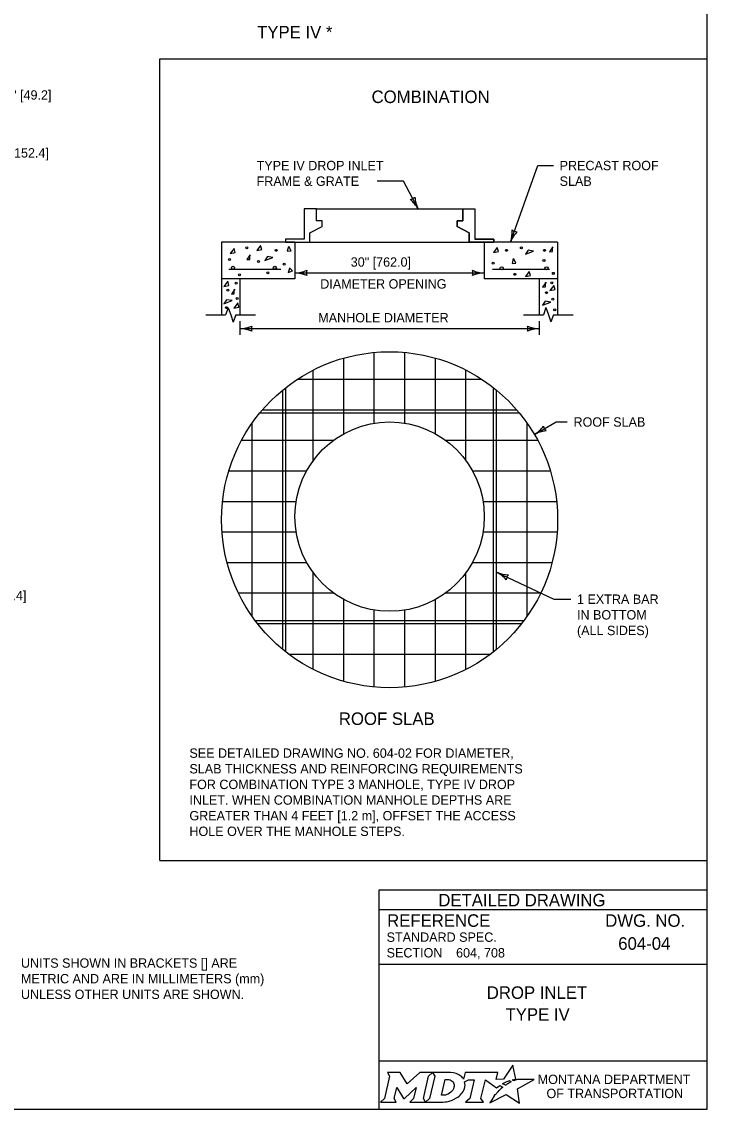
# Model space of a CAD drawing. Extents: x 49991.4 to 50021, y 49987.6 to 50011.4.
# Drawn here: x 50004.23 to 50008.61, y 50000.06 to 50007.02 of the extents above; entities that cross this region are included whole.
import ezdxf

# ---------------------------------------------------------------- set-up
doc = ezdxf.new("R2010")
doc.units = 0
for name, color, linetype in [('Level 1', 7, 'Continuous'), ('Level 2', 7, 'Continuous'), ('Level 3', 7, 'Continuous'), ('Level 6', 7, 'Continuous')]:
    doc.layers.add(name, color=color, linetype=linetype)

msp = doc.modelspace()

# ---------------------------------------------------------------- linework, layer by layer
at = {"layer": 'Level 1'}
for p, q in [((50005.1146, 50006.7794), (50008.6146, 50006.7794)), ((50005.1146, 50001.6533), (50005.1146, 50006.7794)), ((50006.1157, 50005.8205), (50006.0387, 50005.8205)), ((50006.0387, 50005.8205), (50006.0387, 50005.6252)), ((50006.1157, 50005.8205), (50006.0387, 50005.8205)), ((50006.0387, 50005.8205), (50006.0387, 50005.6252)), ((50006.1157, 50005.7436), (50006.1157, 50005.8205)), ((50006.1157, 50005.7436), (50006.1157, 50005.8205)), ((50006.1157, 50005.8205), (50007.0519, 50005.8205)), ((50007.0519, 50005.7436), (50007.0519, 50005.8205)), ((50007.0519, 50005.8205), (50007.1289, 50005.8205)), ((50007.0519, 50005.8205), (50007.0519, 50005.7436)), ((50007.0519, 50005.8205), (50007.1289, 50005.8205)), ((50007.1289, 50005.8205), (50007.1289, 50005.6252)), ((50007.1289, 50005.8205), (50007.1289, 50005.6252)), ((50007.1289, 50005.8205), (50007.1289, 50005.6252)), ((50006.1523, 50005.7436), (50006.1157, 50005.7436)), ((50006.1523, 50005.7436), (50006.1157, 50005.7436)), ((50006.1523, 50005.7062), (50006.1523, 50005.7436)), ((50006.1523, 50005.7062), (50006.1523, 50005.7436)), ((50007.0153, 50005.7062), (50007.0153, 50005.7436)), ((50007.0153, 50005.7436), (50007.0519, 50005.7436)), ((50007.0519, 50005.7436), (50007.0153, 50005.7436)), ((50007.0153, 50005.7436), (50007.0153, 50005.7062)), ((50006.0743, 50005.6671), (50006.1523, 50005.7062)), ((50006.0743, 50005.6671), (50006.1523, 50005.7062)), ((50007.0933, 50005.6671), (50007.0153, 50005.7062)), ((50007.0153, 50005.7062), (50007.0933, 50005.6671)), ((50005.9783, 50005.6078), (50005.5095, 50005.6078)), ((50005.5095, 50005.6078), (50005.5095, 50005.382)), ((50006.0387, 50005.6252), (50005.9179, 50005.6252)), ((50005.9179, 50005.6252), (50005.9179, 50005.6078)), ((50006.0387, 50005.6252), (50005.9179, 50005.6252)), ((50005.9179, 50005.6252), (50005.9179, 50005.6078)), ((50005.9179, 50005.6078), (50006.0743, 50005.6078)), ((50005.9179, 50005.6078), (50006.0743, 50005.6078)), ((50005.9783, 50005.6078), (50005.9783, 50005.3734)), ((50006.0743, 50005.6078), (50006.0743, 50005.6671)), ((50006.0743, 50005.6078), (50006.0743, 50005.6671)), ((50006.0743, 50005.6078), (50007.0933, 50005.6078)), ((50007.0933, 50005.6078), (50007.0933, 50005.6671)), ((50007.0933, 50005.6671), (50007.0933, 50005.6078)), ((50007.2497, 50005.6078), (50007.0933, 50005.6078)), ((50007.0933, 50005.6078), (50007.2497, 50005.6078)), ((50007.1289, 50005.6252), (50007.2497, 50005.6252)), ((50007.2497, 50005.6252), (50007.1289, 50005.6252)), ((50007.6581, 50005.6078), (50007.1893, 50005.6078)), ((50007.1893, 50005.6078), (50007.1893, 50005.3734)), ((50007.2497, 50005.6252), (50007.2497, 50005.6078)), ((50007.2497, 50005.6078), (50007.2497, 50005.6252)), ((50007.6581, 50005.6078), (50007.6581, 50005.382)), ((50007.6575, 50005.5913), (50007.6575, 50005.5913)), ((50005.8895, 50005.432), (50005.5563, 50005.432)), ((50007.6057, 50005.432), (50007.2411, 50005.432)), ((50005.5095, 50005.382), (50005.5095, 50005.1416)), ((50005.9783, 50005.3734), (50005.5095, 50005.3734)), ((50005.6267, 50005.3734), (50005.6267, 50005.1416)), ((50007.6581, 50005.3734), (50007.1893, 50005.3734)), ((50007.5409, 50005.3734), (50007.5409, 50005.1427)), ((50007.6581, 50005.382), (50007.6581, 50005.1427)), ((50006.2909, 50004.382), (50006.2909, 50004.8656)), ((50006.4861, 50004.4496), (50006.4861, 50004.9019)), ((50006.6815, 50004.4496), (50006.6815, 50004.9019)), ((50006.8767, 50004.382), (50006.8767, 50004.8656)), ((50006.0955, 50004.21), (50006.0955, 50004.7889)), ((50007.0721, 50004.2101), (50007.0721, 50004.7889)), ((50005.9957, 50004.731), (50007.172, 50004.731)), ((50005.9003, 50003.0034), (50005.9003, 50004.6608)), ((50005.9197, 50002.9877), (50005.9197, 50004.6764)), ((50007.2479, 50002.9877), (50007.2479, 50004.6764)), ((50007.2675, 50003.0035), (50007.2675, 50004.6607)), ((50005.7555, 50004.5161), (50007.4121, 50004.5161)), ((50005.772, 50004.5356), (50007.3956, 50004.5356)), ((50005.7049, 50003.2145), (50005.7049, 50004.4497)), ((50007.4627, 50003.2144), (50007.4627, 50004.4498)), ((50005.6374, 50004.3403), (50006.2257, 50004.3403)), ((50006.9419, 50004.3403), (50007.5302, 50004.3403)), ((50005.5562, 50004.145), (50006.0539, 50004.145)), ((50007.1137, 50004.145), (50007.6115, 50004.145)), ((50005.516, 50003.9497), (50005.9863, 50003.9497)), ((50007.1814, 50003.9497), (50007.6516, 50003.9497)), ((50005.5124, 50003.7544), (50005.9863, 50003.7544)), ((50007.1814, 50003.7544), (50007.6552, 50003.7544)), ((50005.5449, 50003.5591), (50006.0539, 50003.5591)), ((50007.1137, 50003.5591), (50007.6228, 50003.5591)), ((50006.0955, 50002.8753), (50006.0955, 50003.4941)), ((50007.0721, 50002.8752), (50007.0721, 50003.494)), ((50005.617, 50003.3638), (50006.2258, 50003.3638)), ((50006.2909, 50002.7986), (50006.2909, 50003.3221)), ((50006.8767, 50002.7986), (50006.8767, 50003.3221)), ((50006.9419, 50003.3638), (50007.5506, 50003.3638)), ((50006.4861, 50002.7623), (50006.4861, 50003.2545)), ((50006.6815, 50002.7623), (50006.6815, 50003.2545)), ((50005.7241, 50003.188), (50007.4435, 50003.188)), ((50005.7391, 50003.1684), (50007.4285, 50003.1684)), ((50005.9386, 50002.9732), (50007.229, 50002.9732)), ((50005.1146, 50001.6533), (50008.6146, 50001.6533))]:
    msp.add_line(p, q, dxfattribs=at)
msp.add_lwpolyline([(50008.6146, 50011.2628), (50000.3356, 50011.2628), (50000.3356, 50000.0624), (50008.6146, 50000.0624)], close=True, dxfattribs=at)
for points in [[(50005.5893, 50005.5675), (50005.5641, 50005.5346), (50005.5971, 50005.5409), (50005.5893, 50005.5675)], [(50005.7591, 50005.5863), (50005.7341, 50005.5534), (50005.7671, 50005.5597), (50005.7591, 50005.5863)], [(50005.9367, 50005.58), (50005.9287, 50005.5488), (50005.9539, 50005.5518), (50005.9397, 50005.5785)], [(50007.2723, 50005.5738), (50007.2471, 50005.5409), (50007.2801, 50005.5472), (50007.2723, 50005.5738)], [(50007.4703, 50005.5566), (50007.4531, 50005.53), (50007.5049, 50005.5503), (50007.4687, 50005.5566)], [(50007.6277, 50005.577), (50007.6057, 50005.5456), (50007.6245, 50005.5472), (50007.6245, 50005.5754)], [(50005.6931, 50005.5268), (50005.6711, 50005.4955), (50005.6899, 50005.497), (50005.6899, 50005.5252)], [(50005.8031, 50005.5158), (50005.7857, 50005.4892), (50005.8377, 50005.5096), (50005.8015, 50005.5158)], [(50007.3743, 50005.5017), (50007.3665, 50005.4704), (50007.3915, 50005.4735), (50007.3775, 50005.5001)], [(50005.9429, 50005.4391), (50005.9351, 50005.4141), (50005.9633, 50005.4234), (50005.9429, 50005.4422)], [(50007.4767, 50005.4202), (50007.4517, 50005.3873), (50007.4847, 50005.3936), (50007.4767, 50005.4202)], [(50005.5493, 50005.3566), (50005.5241, 50005.3237), (50005.5571, 50005.33), (50005.5493, 50005.3566)], [(50007.5844, 50005.351), (50007.5624, 50005.3197), (50007.5812, 50005.3212), (50007.5812, 50005.3494)], [(50007.6335, 50005.3308), (50007.6083, 50005.2979), (50007.6413, 50005.3042), (50007.6335, 50005.3308)], [(50005.5943, 50005.3065), (50005.5723, 50005.2752), (50005.5911, 50005.2767), (50005.5911, 50005.3049)], [(50005.542, 50005.2393), (50005.5246, 50005.2127), (50005.5766, 50005.2331), (50005.5404, 50005.2393)], [(50005.6128, 50005.2183), (50005.5876, 50005.1854), (50005.6206, 50005.1917), (50005.6128, 50005.2183)], [(50007.5792, 50005.2299), (50007.5618, 50005.2033), (50007.6138, 50005.2237), (50007.5776, 50005.2299)]]:
    msp.add_lwpolyline(points, dxfattribs=at)
for centre, radius in [((50005.6708, 50005.5706), 0.00629), ((50005.8595, 50005.5549), 0.00629), ((50007.3317, 50005.5549), 0.00629), ((50007.4261, 50005.5706), 0.00629), ((50007.574, 50005.5549), 0.00629), ((50005.5607, 50005.4954), 0.00629), ((50005.7463, 50005.4828), 0.00629), ((50005.9099, 50005.4672), 0.00629), ((50007.2468, 50005.4734), 0.00629), ((50007.5708, 50005.4891), 0.00629), ((50005.583, 50005.443), 0.00994), ((50005.6236, 50005.3982), 0.00629), ((50005.8061, 50005.4107), 0.00629), ((50005.8502, 50005.443), 0.00994), ((50007.3008, 50005.4399), 0.00994), ((50007.3852, 50005.4013), 0.00629), ((50007.5869, 50005.4399), 0.00994), ((50007.6306, 50005.4076), 0.00629), ((50005.6021, 50005.3451), 0.00629), ((50007.6204, 50005.3474), 0.00629), ((50005.5504, 50005.3006), 0.00629), ((50007.5875, 50005.2842), 0.00629), ((50005.5409, 50005.1881), 0.00629), ((50005.6092, 50005.2467), 0.00629), ((50007.6275, 50005.242), 0.00629), ((50007.6393, 50005.174), 0.00629), ((50006.5838, 50003.8321), 1.0742), ((50006.5838, 50003.8521), 0.6055)]:
    msp.add_circle(centre, radius, dxfattribs=at)
at = {"layer": 'Level 2'}
for p, q in [((50008.6146, 50001.4624), (50006.5146, 50001.4624)), ((50006.5146, 50001.4624), (50006.5146, 50000.0624)), ((50008.6146, 50001.3374), (50006.5146, 50001.3374)), ((50008.2507, 50001.1223), (50008.2507, 50001.1223)), ((50007.0089, 50001.0629), (50007.0089, 50001.0629)), ((50008.6146, 50000.9874), (50006.5146, 50000.9874)), ((50007.5646, 50000.7383), (50007.5646, 50000.7383)), ((50008.6146, 50000.3693), (50006.5146, 50000.3693))]:
    msp.add_line(p, q, dxfattribs=at)
for points in [[(50007.3771, 50000.2447), (50007.3668, 50000.2503), (50007.3784, 50000.2531), (50007.39, 50000.2551), (50007.3726, 50000.3452), (50007.3131, 50000.2539), (50007.2658, 50000.2532), (50007.2761, 50000.2973), (50007.0669, 50000.2974), (50007.0568, 50000.2549), (50007.051, 50000.2632)], [(50006.5701, 50000.2974), (50006.5842, 50000.274), (50006.5507, 50000.1307), (50006.525, 50000.1082), (50006.6266, 50000.1082), (50006.6131, 50000.131), (50006.6293, 50000.2011), (50006.673, 50000.1321), (50006.6783, 50000.1321), (50006.7534, 50000.2016), (50006.737, 50000.1305), (50006.7123, 50000.1085), (50006.8139, 50000.1085), (50006.8001, 50000.1318), (50006.8333, 50000.2742)], [(50006.8333, 50000.2742), (50006.8586, 50000.2974), (50006.7762, 50000.2974), (50006.6966, 50000.2244), (50006.6521, 50000.2971), (50006.5701, 50000.2974)], [(50006.9722, 50000.2974), (50006.8586, 50000.2974), (50006.8733, 50000.2745), (50006.8394, 50000.1307), (50006.8139, 50000.1085), (50006.9245, 50000.1085)], [(50006.9962, 50000.2107), (50006.995, 50000.2026), (50006.9918, 50000.1933), (50006.9876, 50000.1851), (50006.982, 50000.1776), (50006.9755, 50000.1707), (50006.9676, 50000.1644), (50006.9593, 50000.1597), (50006.9502, 50000.1558), (50006.9411, 50000.1535), (50006.9319, 50000.1526), (50006.916, 50000.1526), (50006.9396, 50000.2526), (50006.9556, 50000.2526), (50006.9632, 50000.252), (50006.9708, 50000.2501), (50006.9774, 50000.2471), (50006.9835, 50000.2429), (50006.9883, 50000.2379), (50006.992, 50000.2319), (50006.9947, 50000.2257), (50006.9963, 50000.2183), (50006.9963, 50000.2153), (50006.9962, 50000.2107)], [(50007.0636, 50000.2383), (50007.0882, 50000.2514), (50007.1251, 50000.2514), (50007.0965, 50000.1309), (50007.069, 50000.1082), (50007.1852, 50000.1082), (50007.1682, 50000.1311), (50007.1964, 50000.2513), (50007.2677, 50000.1996), (50007.2888, 50000.2147), (50007.3085, 50000.2038)], [(50007.2527, 50000.1479), (50007.2374, 50000.1235), (50007.2327, 50000.116), (50007.2269, 50000.1074), (50007.2246, 50000.1031), (50007.3299, 50000.1562), (50007.4138, 50000.1011), (50007.4007, 50000.1938), (50007.5076, 50000.2522), (50007.4583, 50000.253), (50007.4282, 50000.2534), (50007.4074, 50000.2537), (50007.4006, 50000.2522), (50007.3957, 50000.251), (50007.3873, 50000.2487), (50007.3771, 50000.2447)], [(50007.3267, 50000.2171), (50007.3243, 50000.2154), (50007.306, 50000.225), (50007.3163, 50000.2307), (50007.3204, 50000.2329), (50007.329, 50000.2369), (50007.3347, 50000.2395), (50007.3426, 50000.2425), (50007.3499, 50000.2452), (50007.3617, 50000.2378), (50007.3577, 50000.2357), (50007.3531, 50000.2332), (50007.3489, 50000.231), (50007.3439, 50000.2281), (50007.342, 50000.227), (50007.3393, 50000.2254), (50007.3368, 50000.224), (50007.3345, 50000.2224), (50007.3319, 50000.2206), (50007.3292, 50000.2188), (50007.3267, 50000.2171)], [(50006.9702, 50000.1158), (50006.9786, 50000.1184), (50006.9916, 50000.1238), (50007.012, 50000.1348)], [(50007.2666, 50000.164), (50007.2666, 50000.164)]]:
    msp.add_lwpolyline(points, dxfattribs=at)
for centre, radius, start, end in [((50006.9513, 50000.2363), 0.1183, 300.91025, 339.13831), ((50006.9953, 50000.219), 0.0709, 339.53292, 15.85821)]:
    msp.add_arc(centre, radius, start, end, dxfattribs=at)
for centre, major_axis, ratio, start_param, end_param in [((50006.9701, 50000.25), (0.0834, -0.0037), 0.568097, 0.61298, 1.570796), ((50007.0257, 50000.2573), (0.0361, -0.0295), 0.469099, 1.225588, 1.570796), ((50007.2764, 50000.1742), (-0.0098, -0.0102), 0.016458, 3.141593, 6.279097), ((50007.2974, 50000.1941), (-0.0112, -0.0097), 0.021651, 3.157348, 6.283185), ((50006.9248, 50000.2568), (0, 0.1484), 0.987302, 3.139398, 3.456847), ((50007.2597, 50000.1559), (-0.00694, -0.00806), 0.008222, 0, 3.137361)]:
    msp.add_ellipse(centre, major_axis=major_axis, ratio=ratio, start_param=start_param, end_param=end_param, dxfattribs=at)
at = {"layer": 'Level 3'}
for p, q in [((50007.3574, 50005.6078), (50007.5309, 50006.0971)), ((50007.5309, 50006.0971), (50007.6309, 50006.0971)), ((50006.6726, 50005.9971), (50006.5041, 50005.9971)), ((50006.7659, 50005.8205), (50006.6726, 50005.9971)), ((50005.9783, 50005.4102), (50007.1893, 50005.4102)), ((50005.6267, 50005.1016), (50005.6267, 50005.014)), ((50005.6267, 50005.054), (50007.5409, 50005.054)), ((50007.5409, 50005.1027), (50007.5409, 50005.014)), ((50007.5093, 50004.3775), (50007.6496, 50004.4571)), ((50007.6496, 50004.4571), (50007.7196, 50004.4571)), ((50007.2675, 50003.4963), (50007.6328, 50003.3241)), ((50007.6328, 50003.3241), (50007.742, 50003.3241))]:
    msp.add_line(p, q, dxfattribs=at)
for centre, radius, start, end in [((50006.706, 50005.9339), 0.0548, 279.98359, 315.70595), ((50006.9666, 50005.9162), 0.2223, 185.30078, 205.48429), ((50006.5655, 50005.7016), 0.233, 30.67208, 49.92193), ((50007.1343, 50005.6747), 0.233, 343.30702, 2.55687), ((50007.5637, 50005.5249), 0.2223, 137.93572, 158.11923), ((50007.4003, 50005.7286), 0.0548, 232.61853, 268.34089), ((50005.9668, 50005.6429), 0.233, 272.82731, 292.07716), ((50005.9691, 50005.1881), 0.2223, 67.45601, 87.63952), ((50006.1065, 50005.4102), 0.0548, 162.13882, 197.86118), ((50007.1985, 50005.6323), 0.2223, 247.45601, 267.63952), ((50007.0611, 50005.4102), 0.0548, 342.13882, 17.86118), ((50007.2008, 50005.1775), 0.233, 92.82731, 112.07716), ((50005.6152, 50005.2867), 0.233, 272.82731, 292.07716), ((50005.6175, 50004.8319), 0.2223, 67.45601, 87.63952), ((50005.7549, 50005.054), 0.0548, 162.13882, 197.86118), ((50007.5501, 50005.2761), 0.2223, 247.45601, 267.63952), ((50007.4127, 50005.054), 0.0548, 342.13882, 17.86118), ((50007.5524, 50004.8213), 0.233, 92.82731, 112.07716), ((50007.3844, 50004.5742), 0.233, 302.41088, 321.66073), ((50007.6208, 50004.4408), 0.0548, 191.72239, 227.44475), ((50007.611, 50004.1798), 0.2223, 97.03958, 117.22309), ((50007.1645, 50003.2993), 0.2223, 42.21713, 62.40064), ((50007.3563, 50003.7117), 0.233, 247.58843, 266.83828), ((50007.3835, 50003.4416), 0.0548, 136.89994, 172.6223)]:
    msp.add_arc(centre, radius, start, end, dxfattribs=at)
at = {"layer": 'Level 6'}
for p, q in [((50005.5519, 50005.1873), (50005.5357, 50005.1416)), ((50005.5519, 50005.1873), (50005.5681, 50005.1416)), ((50007.5833, 50005.1884), (50007.5671, 50005.1427)), ((50007.5833, 50005.1884), (50007.5995, 50005.1427)), ((50005.4095, 50005.1416), (50005.5357, 50005.1416)), ((50005.5681, 50005.1416), (50005.5843, 50005.0959)), ((50005.6005, 50005.1416), (50005.5843, 50005.0959)), ((50005.6005, 50005.1416), (50005.7267, 50005.1416)), ((50007.4409, 50005.1427), (50007.5671, 50005.1427)), ((50007.5995, 50005.1427), (50007.6157, 50005.097)), ((50007.6319, 50005.1427), (50007.6157, 50005.097)), ((50007.6319, 50005.1427), (50007.7581, 50005.1427))]:
    msp.add_line(p, q, dxfattribs=at)

# ---------------------------------------------------------------- texts
at = {"layer": 'Level 2'}
for s, height, p in [('TYPE IV *', 0.08, (50005.737, 50006.9104)), ('1 15/16" [49.2]', 0.06, (50003.9029, 50006.5183)), ('COMBINATION', 0.08, (50006.4686, 50006.4967)), ('6" [152.4]', 0.06, (50004.0651, 50006.148)), ('TYPE IV DROP INLET', 0.06, (50005.7338, 50006.0671)), ('PRECAST ROOF ', 0.06, (50007.6709, 50006.0671)), ('FRAME & GRATE', 0.06, (50005.7338, 50005.9671)), ('SLAB', 0.06, (50007.6709, 50005.9671)), ('30" [762.0] ', 0.06, (50006.3355, 50005.4502)), ('DIAMETER OPENING', 0.06, (50006.1407, 50005.3102)), ('MANHOLE DIAMETER', 0.06, (50006.1279, 50005.094)), ('ROOF SLAB', 0.06, (50007.7596, 50004.4271)), ('6" [152.4]', 0.06, (50003.9212, 50003.3171)), ('1 EXTRA BAR', 0.06, (50007.782, 50003.2941)), ('IN BOTTOM', 0.06, (50007.782, 50003.1941)), ('(ALL SIDES)', 0.06, (50007.782, 50003.0941)), ('ROOF SLAB', 0.08, (50006.2595, 50002.5197)), ('SEE DETAILED DRAWING NO. 604-02 FOR DIAMETER,', 0.06, (50005.3041, 50002.3097)), ('SLAB THICKNESS AND REINFORCING REQUIREMENTS', 0.06, (50005.3041, 50002.2097)), ('FOR COMBINATION TYPE 3 MANHOLE, TYPE IV DROP', 0.06, (50005.3041, 50002.1097)), ('INLET. WHEN COMBINATION MANHOLE DEPTHS ARE', 0.06, (50005.3041, 50002.0097)), ('GREATER THAN 4 FEET [1.2 m], OFFSET THE ACCESS ', 0.06, (50005.3041, 50001.9097)), ('HOLE OVER THE MANHOLE STEPS.', 0.06, (50005.3041, 50001.8097)), ('DETAILED DRAWING', 0.0799, (50006.8956, 50001.3599)), ('REFERENCE', 0.08, (50006.5682, 50001.229)), ('DWG. NO.', 0.08, (50007.9624, 50001.229)), ('STANDARD SPEC.', 0.06, (50006.5649, 50001.133)), ('604-04', 0.08, (50008.0456, 50001.0823)), ('SECTION', 0.06, (50006.5649, 50001.033)), ('604, 708', 0.06, (50007.0089, 50001.0329)), ('UNITS SHOWN IN BRACKETS [] ARE ', 0.06, (50004.2272, 50000.9673)), ('METRIC AND ARE IN MILLIMETERS (mm) ', 0.06, (50004.2272, 50000.8673)), ('UNLESS OTHER UNITS ARE SHOWN.', 0.06, (50004.2272, 50000.7673)), ('DROP INLET', 0.08, (50007.2052, 50000.7683)), ('TYPE IV', 0.08, (50007.325, 50000.6283)), ('MONTANA DEPARTMENT', 0.06, (50007.5308, 50000.2236)), ('OF TRANSPORTATION', 0.06, (50007.587, 50000.1336))]:
    msp.add_text(s, height=height, dxfattribs=at).set_placement(p)

doc.saveas('drawing.dxf')
